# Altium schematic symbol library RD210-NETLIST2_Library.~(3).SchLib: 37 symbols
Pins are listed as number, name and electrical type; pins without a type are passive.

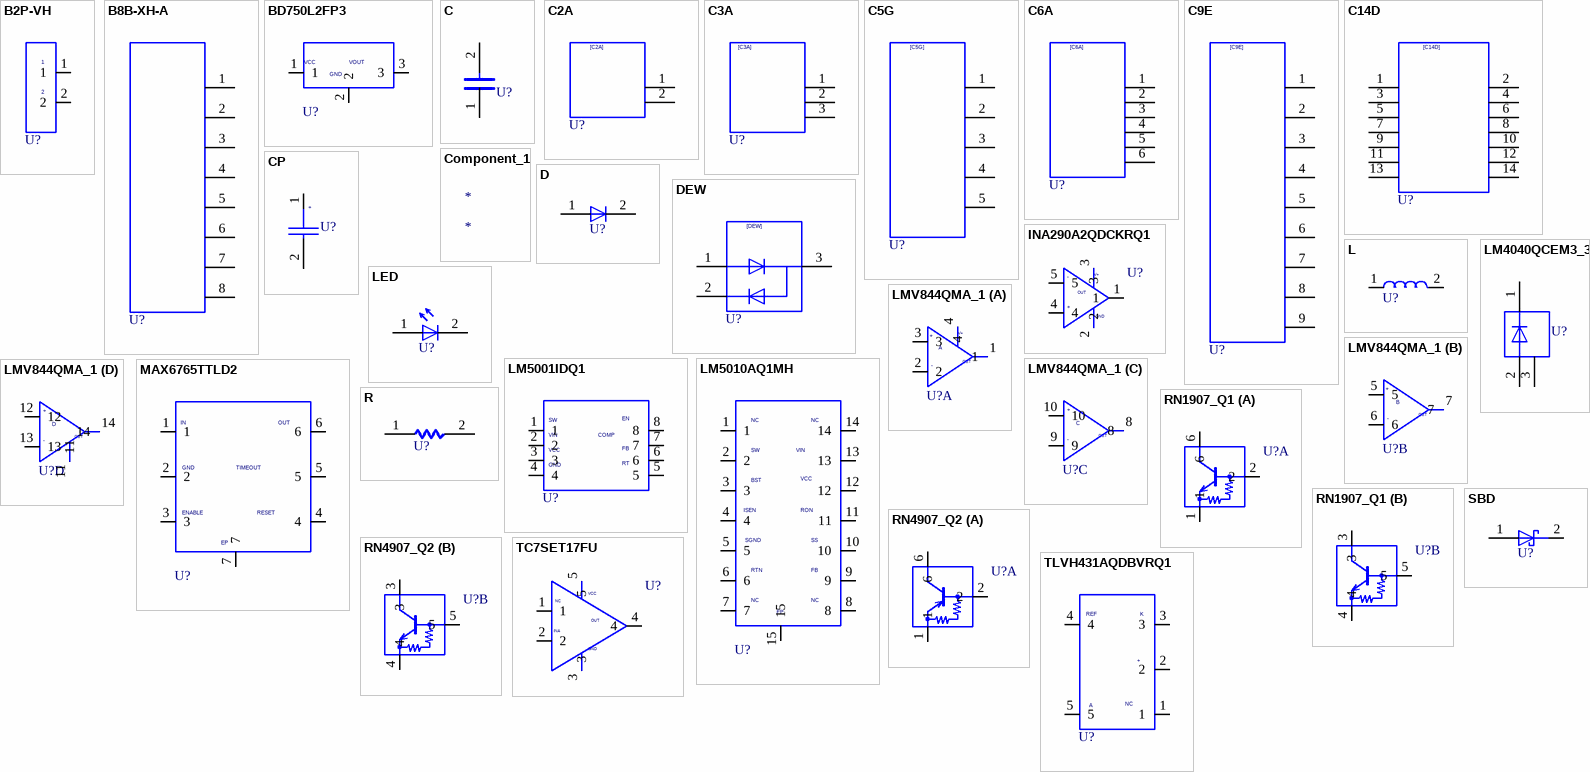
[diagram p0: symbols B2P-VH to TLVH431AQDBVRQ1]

## B2P-VH
designator U?  (value not drawn)
MANUFACTURER: PHOENIX CONTACT; ITEM: Connector 2Pin Terminal Block; SCH_NAME: MCV1,5/2-G-3.5; TIME: 08:44:48; UPDATEUSER: sptcae13; UPDATETIME: 17:31:47; SAVECOUNT: 5; SAVEAREA0: -87042,-47887,89765,32676; OriginalSymbolOrigin: (0,0); Altium-Right: 20; Altium-Bottom: 60
pins: 1, 2

## B8B-XH-A
designator U?  (value not drawn)
MANUFACTURER: AVX; ITEM: CAP Ceramic; VAL2: 100V; SIZECODESMD: 1608; VALUE4: NP0; VAL1: 150p; TIME: 08:44:46; UPDATEUSER: sptcae13; UPDATETIME: 13:09:45; SAVECOUNT: 4; SAVEAREA0: -63668,-57919,68911,14627; OriginalSymbolOrigin: (0,0); Altium-Right: 50; Altium-Bottom: 180
pins: 1, 2, 3, 4, 5, 6, 7, 8

## BD750L2FP3
designator U?  (value not drawn)
MANUFACTURER: PANASONIC; ITEM: CAP Film; TIME: 08:44:47; UPDATEUSER: sptcae13; UPDATETIME: 11:25:10; SAVECOUNT: 4; SAVEAREA0: -24389,-27959,34535,4284; OriginalSymbolOrigin: (2540,0); Altium-Right: 60; Altium-Bottom: 30
pins: 1, 2, 3

## C
designator U?  (value not drawn)
OriginalSymbolOrigin: (2540,7620); Altium-Right: 20; Altium-Bottom: 10
pins: 1, 2

## C2A
designator U?  (value not drawn)
SAVEAREA0: -4611,-206,24632,18258; SAVECOUNT: 25; TIME: 13:28:28; UPDATEUSER: tomizawa-y; UPDATETIME: 12:08:31; OriginalSymbolOrigin: (2540,15240); Altium-Right: 50
pins: 1, 2

## C3A
designator U?  (value not drawn)
SAVEAREA0: -6798,-236,26764,20869; TIME: 09:53:04; UPDATEUSER: tomizawa-y; UPDATETIME: 09:53:12; SAVECOUNT: 2; OriginalSymbolOrigin: (2540,17780); Altium-Right: 50; Altium-Bottom: 60
pins: 1, 2, 3

## C5G
designator U?  (value not drawn)
SAVEAREA0: -54324,-10433,76651,49246; TIME: 08:44:29; UPDATEUSER: w90028dm; UPDATETIME: 15:50:21; SAVECOUNT: 7; OriginalSymbolOrigin: (5080,35560); Altium-Right: 50; Altium-Bottom: 130
pins: 1, 2, 3, 4, 5

## C6A
designator U?  (value not drawn)
SAVEAREA0: -13050,-324,32905,28692; SAVECOUNT: 22; TIME: 13:28:28; UPDATEUSER: tomizawa-y; UPDATETIME: 10:39:55; OriginalSymbolOrigin: (2540,25400); Altium-Right: 50; Altium-Bottom: 90
pins: 1, 2, 3, 4, 5, 6

## C9E
designator U?  (value not drawn)
SAVEAREA0: -48823,-644,68147,57583; TIME: 12:01:18; UPDATEUSER: 19990028; UPDATETIME: 10:28:58; SAVECOUNT: 6; OriginalSymbolOrigin: (2540,53340); Altium-Right: 50; Altium-Bottom: 200
pins: 1, 2, 3, 4, 5, 6, 7, 8, 9

## C14D
designator U?  (value not drawn)
SAVEAREA0: -12827,-359,38319,30760; TIME: 17:50:57; UPDATEUSER: 19990028; UPDATETIME: 16:59:26; SAVECOUNT: 5; OriginalSymbolOrigin: (5080,27940); Altium-Right: 60; Altium-Bottom: 100
pins: 1, 2, 3, 4, 5, 6, 7, 8, 9, 10, 11, 12, 13, 14

## Component_1
designator *

## CP
designator U?  (value not drawn)
SAVEAREA0: -1450,-153,20294,13055; SAVECOUNT: 52; TIME: 15:02:55; UPDATEUSER: fukuda-y; UPDATETIME: 16:13:42; OriginalSymbolOrigin: (2540,10160); Altium-Right: 20
pins: 1 2, 2 1

## D
designator U?  (value not drawn)
SAVEAREA0: -225,-91,12804,7836; SAVECOUNT: 3; TIME: 14:49:55; UPDATEUSER: 19870035; UPDATETIME: 14:20:16; OriginalSymbolOrigin: (5080,5080); Altium-Right: 10; Altium-Bottom: 20
pins: 1 A, 2 C

## DEW
designator U?  (value not drawn)
SAVEAREA0: -10024,-234,32508,20938; TIME: 14:49:55; UPDATEUSER: 19990028; UPDATETIME: 14:00:58; SAVECOUNT: 4; OriginalSymbolOrigin: (5080,17780); Altium-Right: 50; Altium-Bottom: 60
pins: 1 A, 2 C, 3 AC

## INA290A2QDCKRQ1
designator U?  (value not drawn)
MANUFACTURER: TOSHIBA; ITEM: IC Logic; TIME: 08:44:45; UPDATEUSER: sptcae13; UPDATETIME: 08:56:52; SAVECOUNT: 17; SAVEAREA0: -4733,-13253,17562,3068; OriginalSymbolOrigin: (2540,0); Altium-Right: 30; Altium-Bottom: 40
pins: 1, 2, 3, 4, 5

## L
designator U?  (value not drawn)
OriginalSymbolOrigin: (2540,5080); Altium-Right: 30; Altium-Bottom: 20
pins: 1, 2

## LED
designator U?  (value not drawn)
SAVEAREA0: -6799,-183,19247,15664; TIME: 14:49:55; UPDATEUSER: fukuda-y; UPDATETIME: 13:54:07; SAVECOUNT: 4; OriginalSymbolOrigin: (5080,7620); Altium-Right: 10; Altium-Bottom: 30
pins: 1 A, 2 C

## LM4040QCEM3_3
designator U?  (value not drawn)
7TH PART FIELD: RES.,; 4TH PART FIELD: VISHAY,; 3RD PART FIELD: CHIP; 2ND PART FIELD: 1-5%; 5TH PART FIELD: CRCW0805---RT6; 1ST PART FIELD: 1/8W; TIME: 08:44:45; UPDATEUSER: sptcae13; UPDATETIME: 10:00:08; SAVECOUNT: 4; SAVEAREA0: -29906,-23716,24621,6120; OriginalSymbolOrigin: (2540,-5080); Altium-Right: 30
pins: 1, 2, 3

## LM5001IDQ1
designator U?  (value not drawn)
MANUFACTURER: Panasonic; ITEM: Register; SIZECODESMD: 1608; VLUE4: (B); TIME: 08:44:47; UPDATEUSER: sptcae13; UPDATETIME: 14:02:03; SAVECOUNT: 4; SAVEAREA0: -6176,-15431,28749,482; OriginalSymbolOrigin: (2540,0); Altium-Right: 70; Altium-Bottom: 60
pins: 1, 2, 3, 4, 5, 6, 7, 8

## LM5010AQ1MH
designator U?  (value not drawn)
MANUFACTURER: MURATA; ITEM: CAP Ceramic; SIZECODESMD: 1005; VALUE4: X7R; TIME: 08:44:45; UPDATEUSER: sptcae13; UPDATETIME: 15:58:38; SAVECOUNT: 5; SAVEAREA0: -56454,-69958,102754,17159; OriginalSymbolOrigin: (2540,0); Altium-Right: 70; Altium-Bottom: 150
pins: 1, 2, 3, 4, 5, 6, 7, 8, 9, 10, 11, 12, 13, 14, 15

## LMV844QMA_1
designator U?  (value not drawn)
MANUFACTURER: TOSHIBA; ITEM: IC Logic; TIME: 08:44:45; UPDATEUSER: sptcae13; UPDATETIME: 10:49:44; SAVECOUNT: 16; SAVEAREA0: -32882,-28250,45692,7552; OriginalSymbolOrigin: (2540,0); Altium-Right: 40
part A pins: 1, 2, 3, 4
part B pins: 5, 6, 7
part C pins: 8, 9, 10
part D pins: 11, 12, 13, 14

## MAX6765TTLD2
designator U?  (value not drawn)
MANUFACTURER: Panasonic; ITEM: Register; SIZECODESMD: 1608; VLUE4: (B); TIME: 08:44:47; UPDATEUSER: t4887876; UPDATETIME: 18:30:10; SAVECOUNT: 9; SAVEAREA0: -27917,-34385,50659,1418; OriginalSymbolOrigin: (2540,0); Altium-Right: 90; Altium-Bottom: 100
pins: 1, 2, 3, 4, 5, 6, 7

## R
designator U?  (value not drawn)
OriginalSymbolOrigin: (5080,5080); Altium-Right: 20
pins: 1, 2

## RN1907_Q1
designator U?  (value not drawn)
7TH PART FIELD: RES.,; 4TH PART FIELD: VISHAY,; 3RD PART FIELD: CHIP; 2ND PART FIELD: 1-5%; 5TH PART FIELD: CRCW0805---RT6; 1ST PART FIELD: 1/8W; PARTS: 1; VAL1: VALUE; TIME: 08:44:45; UPDATEUSER: t4887876; UPDATETIME: 18:58:36; SAVECOUNT: 11; CLASS: DISCRETE; HETERO: RN4905_1,RN4905_2; FUNCTION: PNP&NPN_PCT; LEVEL: STD; P/D_NUM: TOSHIBA; PKG_TYPE: 2-2J1A; DEVICE: RN4905; SAVEAREA0: -13854,-30480,41847,0; DEVICENAME: DTC144EETL; OriginalSymbolOrigin: (0,12700); Altium-Right: 40
part A pins: 1, 2, 6
part B pins: 3, 4, 5

## RN4907_Q2
designator U?  (value not drawn)
7TH PART FIELD: RES.,; 4TH PART FIELD: VISHAY,; 3RD PART FIELD: CHIP; 2ND PART FIELD: 1-5%; 5TH PART FIELD: CRCW0805---RT6; 1ST PART FIELD: 1/8W; PARTS: 1; VAL1: VALUE; TIME: 08:44:45; UPDATEUSER: t4887876; UPDATETIME: 19:03:09; SAVECOUNT: 13; CLASS: DISCRETE; HETERO: RN4905_1,RN4905_2; FUNCTION: PNP&NPN_PCT; LEVEL: STD; P/D_NUM: TOSHIBA; PKG_TYPE: 2-2J1A; DEVICE: RN4905; SAVEAREA0: -13854,-30480,41847,0; DEVICENAME: DTC144EETL; OriginalSymbolOrigin: (0,12700); Altium-Right: 40
part A pins: 1, 2, 6
part B pins: 3, 4, 5

## SBD
designator U?  (value not drawn)
SAVEAREA0: -4630,-153,17114,13055; TIME: 14:49:55; UPDATEUSER: fukuda-y; UPDATETIME: 08:16:22; SAVECOUNT: 9; OriginalSymbolOrigin: (5080,5080); Altium-Right: 20
pins: 1 A, 2 C

## TC7SET17FU
designator U?  (value not drawn)
MANUFACTURER: WURTH; ITEM: Transformer; VAL2: Np:Ns1:Ns2:Ns3:Ns4:Naux=2.2:2:2:2:2:1; VAL1: 750342424; TIME: 08:44:46; UPDATEUSER: sptcae13; UPDATETIME: 17:58:26; SAVECOUNT: 5; SAVEAREA0: -63459,-44161,77282,32851; OriginalSymbolOrigin: (2540,0); Altium-Right: 50; Altium-Bottom: 60
pins: 1 (io), 2, 3, 4, 5

## TLVH431AQDBVRQ1
designator U?  (value not drawn)
MANUFACTURER: Panasonic; ITEM: Register; SIZECODESMD: 1608; VLUE4: (B); TIME: 08:44:47; UPDATEUSER: sptcae13; UPDATETIME: 17:49:34; SAVECOUNT: 11; SAVEAREA0: -8264,-23317,25334,1279; OriginalSymbolOrigin: (2540,0); Altium-Right: 50; Altium-Bottom: 90
pins: 1, 2, 3, 4, 5

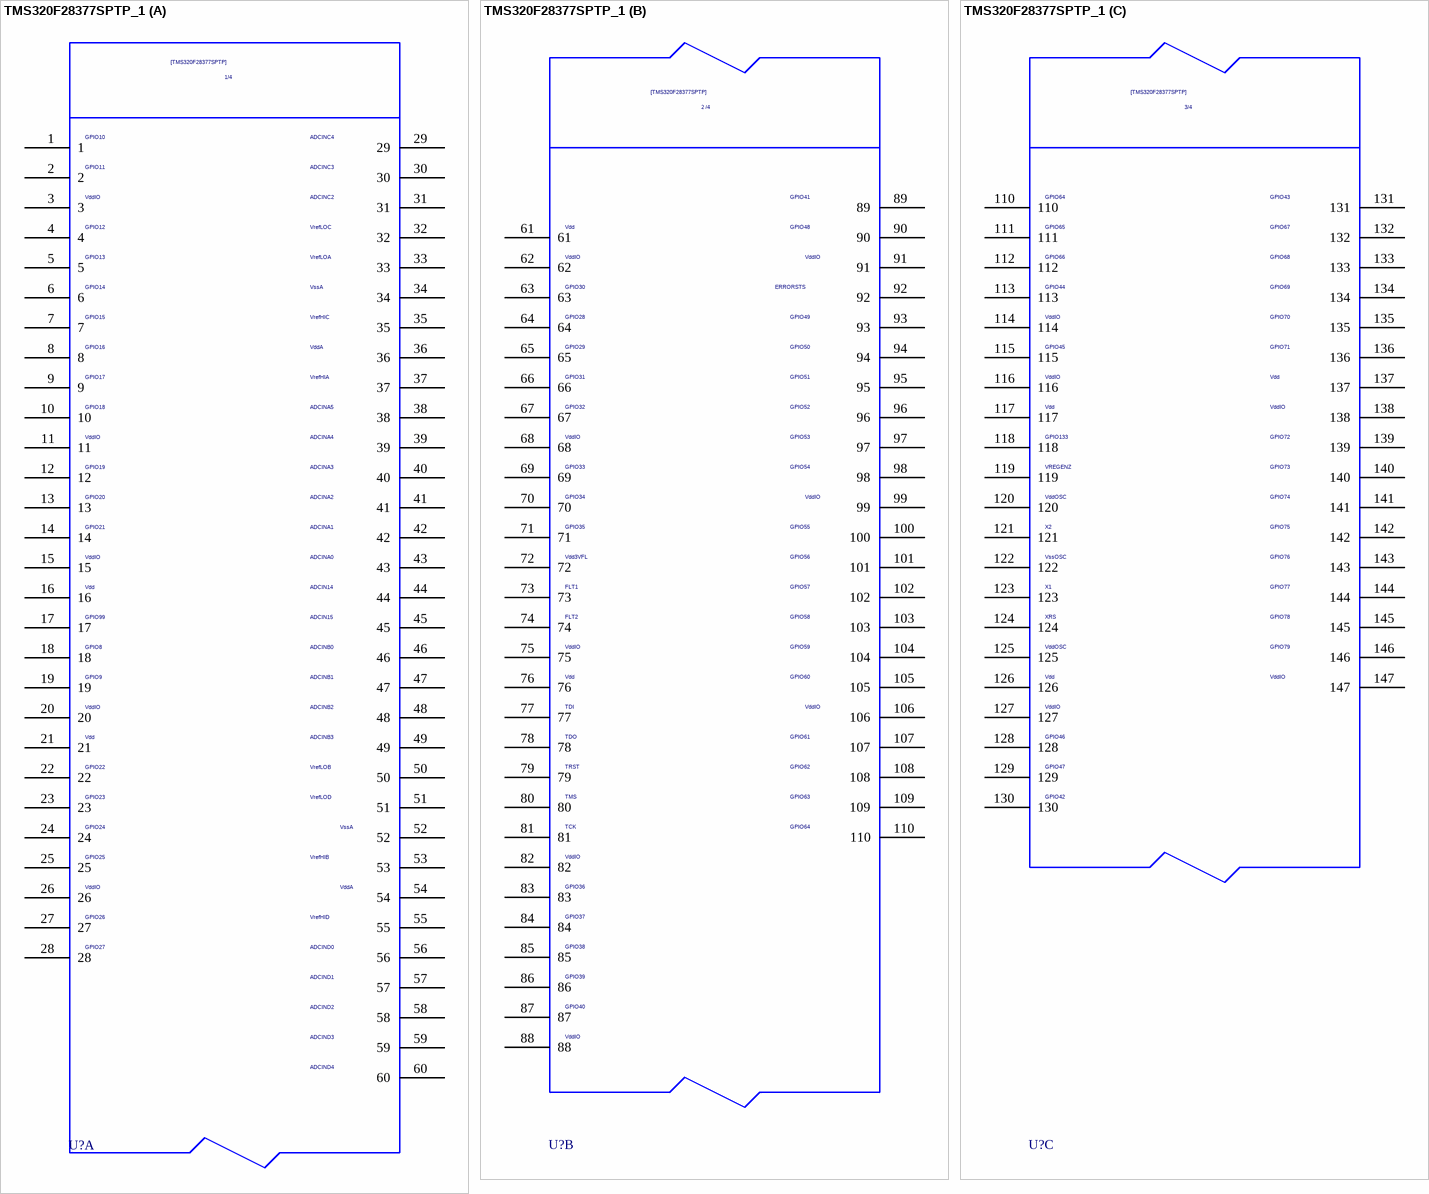
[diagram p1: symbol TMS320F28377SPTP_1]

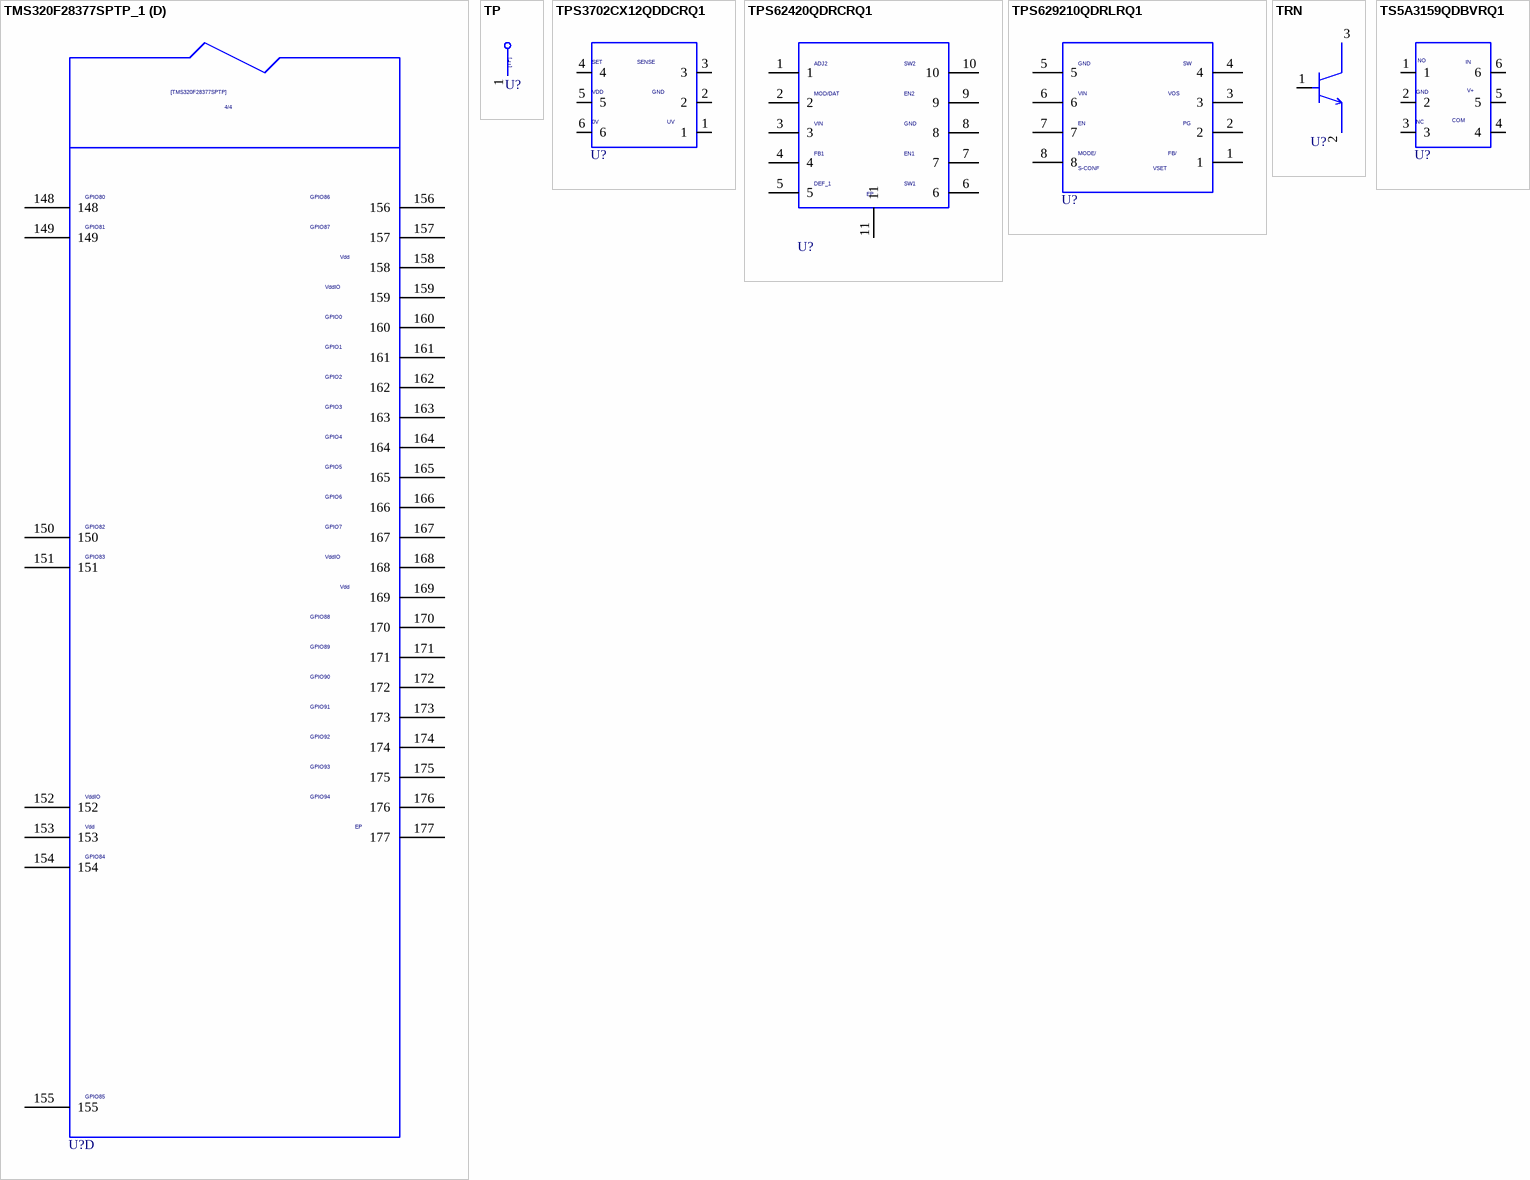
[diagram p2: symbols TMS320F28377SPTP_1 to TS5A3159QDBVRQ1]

## TMS320F28377SPTP_1
designator U?  (value not drawn)
TIME: 14:21:47; UPDATEUSER: sptcae13; UPDATETIME: 11:28:17; SAVECOUNT: 36; SAVEAREA0: -107962,-126732,184126,6359; OriginalSymbolOrigin: (7620,0); Altium-Right: 220; Altium-Bottom: 750; Altium-Bottom1: 710; Altium-Bottom2: 560; Altium-Bottom3: 730
part A pins: 1, 2, 3, 4, 5, 6, 7, 8, 9, 10, 11, 12, 13, 14, 15, 16, 17, 18, 19, 20, 21, 22, 23, 24, 25, 26, 27, 28, 29, 30, 31, 32, 33, 34, 35, 36, 37, 38, 39, 40, 41, 42, 43, 44, 45, 46, 47, 48, 49, 50, 51, 52, 53, 54, 55, 56, 57, 58, 59, 60
part B pins: 61, 62, 63, 64, 65, 66, 67, 68, 69, 70, 71, 72, 73, 74, 75, 76, 77, 78, 79, 80, 81, 82, 83, 84, 85, 86, 87, 88, 89, 90, 91, 92, 93, 94, 95, 96, 97, 98, 99, 100, 101, 102, 103, 104, 105, 106, 107, 108, 109, 110
part C pins: 110, 111, 112, 113, 114, 115, 116, 117, 118, 119, 120, 121, 122, 123, 124, 125, 126, 127, 128, 129, 130, 131, 132, 133, 134, 135, 136, 137, 138, 139, 140, 141, 142, 143, 144, 145, 146, 147
part D pins: 148, 149, 150, 151, 152, 153, 154, 155, 156, 157, 158, 159, 160, 161, 162, 163, 164, 165, 166, 167, 168, 169, 170, 171, 172, 173, 174, 175, 176, 177

## TP
designator U?  (value not drawn)
TIME: 16:12:21; UPDATEUSER: fukuda-y; UPDATETIME: 16:18:11; SAVECOUNT: 2; SAVEAREA0: -242,-92,12810,7836; OriginalSymbolOrigin: (0,7620); Altium-Right: 20; Altium-Bottom: 30
pins: 1

## TPS3702CX12QDDCRQ1
designator U?  (value not drawn)
MANUFACTURER: PHOENIX CONTACT; ITEM: Connector 2Pin Terminal Block; COMP: 1843606; SCH_NAME: MCV1,5/2-G-3.5; ゴン長さ: Short; TIME: 08:44:48; UPDATEUSER: sptcae13; UPDATETIME: 14:58:53; SAVECOUNT: 4; SAVEAREA0: -8061,-17780,30959,0; OriginalSymbolOrigin: (2540,0); Altium-Right: 70
pins: 1, 2, 3, 4, 5, 6

## TPS62420QDRCRQ1
designator U?  (value not drawn)
MANUFACTURER: Panasonic; ITEM: Register; VAL2: 1/10W; SIZECODESMD: 1608; VALUE4: (B); VAL1: 4.99k; TIME: 08:44:47; UPDATEUSER: sptcae13; UPDATETIME: 20:00:27; SAVECOUNT: 8; SAVEAREA0: -17963,-39434,54634,13711; OriginalSymbolOrigin: (5080,0); Altium-Right: 100; Altium-Bottom: 110
pins: 1, 2, 3, 4, 5, 6, 7, 8, 9, 10, 11

## TPS629210QDRLRQ1
designator U?  (value not drawn)
MANUFACTURER: Panasonic; ITEM: Register; VAL2: 1/10W; SIZECODESMD: 1608; VALUE4: (B); COMP: ERA3AEB4991V; VAL1: 4.99k; TIME: 08:44:47; UPDATEUSER: sptcae13; UPDATETIME: 13:49:45; SAVECOUNT: 4; SAVEAREA0: -66056,-44069,81279,36552; OriginalSymbolOrigin: (5080,0); Altium-Right: 100
pins: 1, 2, 3, 4, 5, 6, 7, 8

## TRN
designator U?  (value not drawn)
TIME: 09:39:04; UPDATEUSER: 19910145; UPDATETIME: 15:12:10; SAVECOUNT: 8; SAVEAREA0: -6194,-158,18648,15662; OriginalSymbolOrigin: (2540,17780); Altium-Right: 20; Altium-Bottom: 80
pins: 1 B, 2 E, 3 C

## TS5A3159QDBVRQ1
designator U?  (value not drawn)
MANUFACTURER: Panasonic; ITEM: Register; SIZECODESMD: 1608; VLUE4: (B); TIME: 08:44:47; UPDATEUSER: sptcae13; UPDATETIME: 19:09:10; SAVECOUNT: 15; SAVEAREA0: -8264,-23317,25334,1279; OriginalSymbolOrigin: (2540,0); Altium-Right: 50; Altium-Bottom: 70
pins: 1, 2, 3, 4, 5, 6

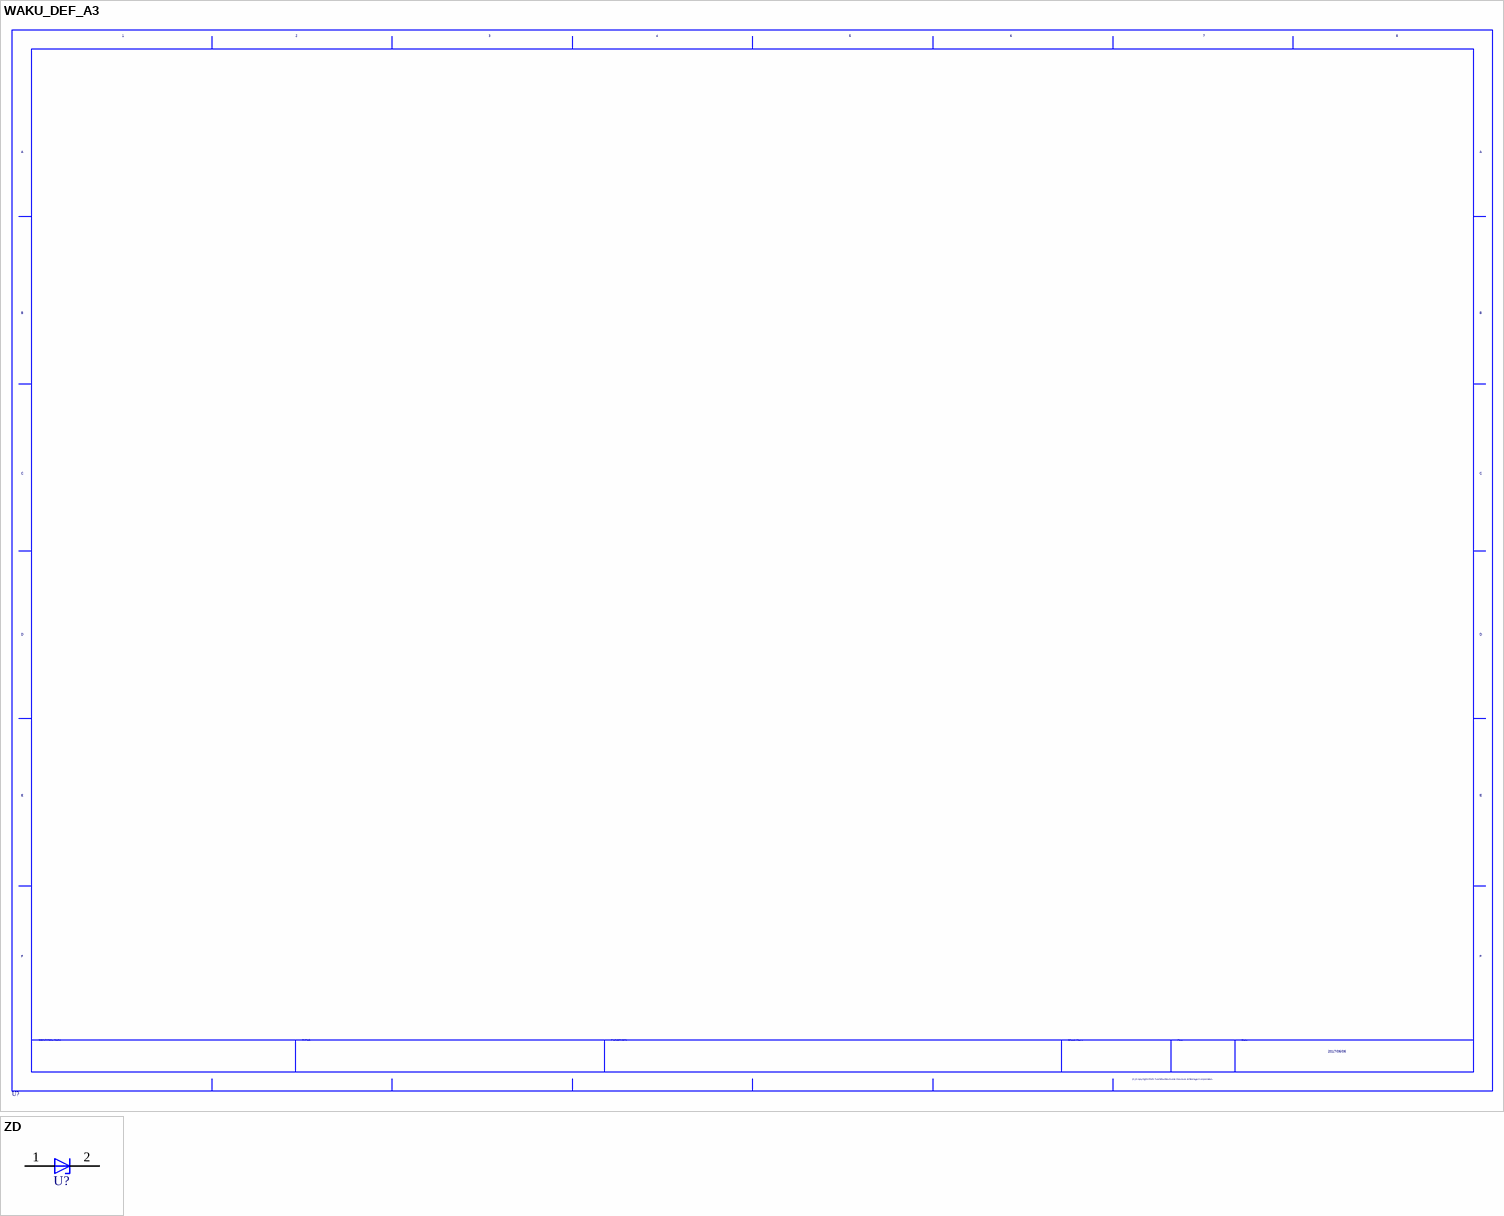
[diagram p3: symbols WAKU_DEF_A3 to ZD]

## WAKU_DEF_A3
designator U?  DATE: 2017/06/06  (hidden comment: WAKU_DEF_A3)
PLOTTIME: HH:MM; SAVEAREA0: 96913,-567914,509243,-368858; TIME: 14:30:25; UPDATEUSER: t5459927; UPDATETIME: 14:05:42; SAVECOUNT: 20; ZONEOFFSETX: 36; ZONEOFFSETY: -24; OriginalSymbolOrigin: (12700,-12700); Altium-Right: 2300; Altium-Bottom: 1650

## ZD
designator U?  (value not drawn)
SAVEAREA0: -4630,-153,17114,13055; TIME: 14:49:55; UPDATEUSER: fukuda-y; UPDATETIME: 08:18:42; SAVECOUNT: 6; OriginalSymbolOrigin: (5080,5080); Altium-Right: 10; Altium-Bottom: 20
pins: 1 A, 2 C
